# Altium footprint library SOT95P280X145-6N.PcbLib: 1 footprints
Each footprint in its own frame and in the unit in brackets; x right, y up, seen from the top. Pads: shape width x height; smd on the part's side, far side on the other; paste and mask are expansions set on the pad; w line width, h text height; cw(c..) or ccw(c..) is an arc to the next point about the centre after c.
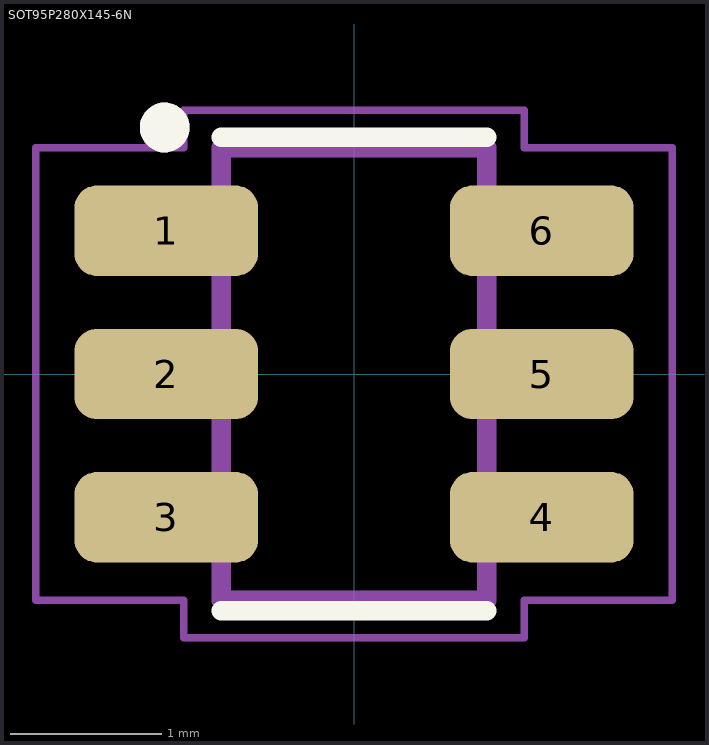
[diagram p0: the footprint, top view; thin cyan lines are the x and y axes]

## SOT95P280X145-6N [mm]
pads (6):
  rrect50% 1.22x0.6 smd: 1(-1.245,0.95) 2(-1.245,0) 3(-1.245,-0.95) 4(1.245,-0.95) 5(1.245,0) 6(1.245,0.95)
Top Overlay:
  circle w0.178: c-1.255,1.635 r0.076
  lines w0.127: -0.88,-1.57 0.88,-1.57 ; -0.88,1.57 0.88,1.57
Mechanical 13:
  circle w0.178: c-1.255,1.635 r0.076
  lines w0.127: -0.88,-1.5 0.88,-1.5 0.88,1.5 -0.88,1.5 -0.88,-1.5
Mechanical 15:
  lines w0.05: -2.11,-1.5 -2.11,1.5 -1.13,1.5 -1.13,1.75 1.13,1.75 1.13,1.5 2.11,1.5 2.11,-1.5 1.13,-1.5 1.13,-1.75 -1.13,-1.75 -1.13,-1.5 -2.11,-1.5
3D body "step_temp.STEP": height 1, standoff 0, extent -1.45,-1.45 1.45,1.45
